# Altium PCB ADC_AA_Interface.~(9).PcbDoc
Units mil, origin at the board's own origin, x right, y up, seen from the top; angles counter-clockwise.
Board outline 2600 x 10000 mil, 6 copper layers (Top Layer, InternalPlane1, MidLayer1, InternalPlane2, InternalPlane3, Bottom Layer); 10 components, 66 nets, 246 pads, 0 vias.
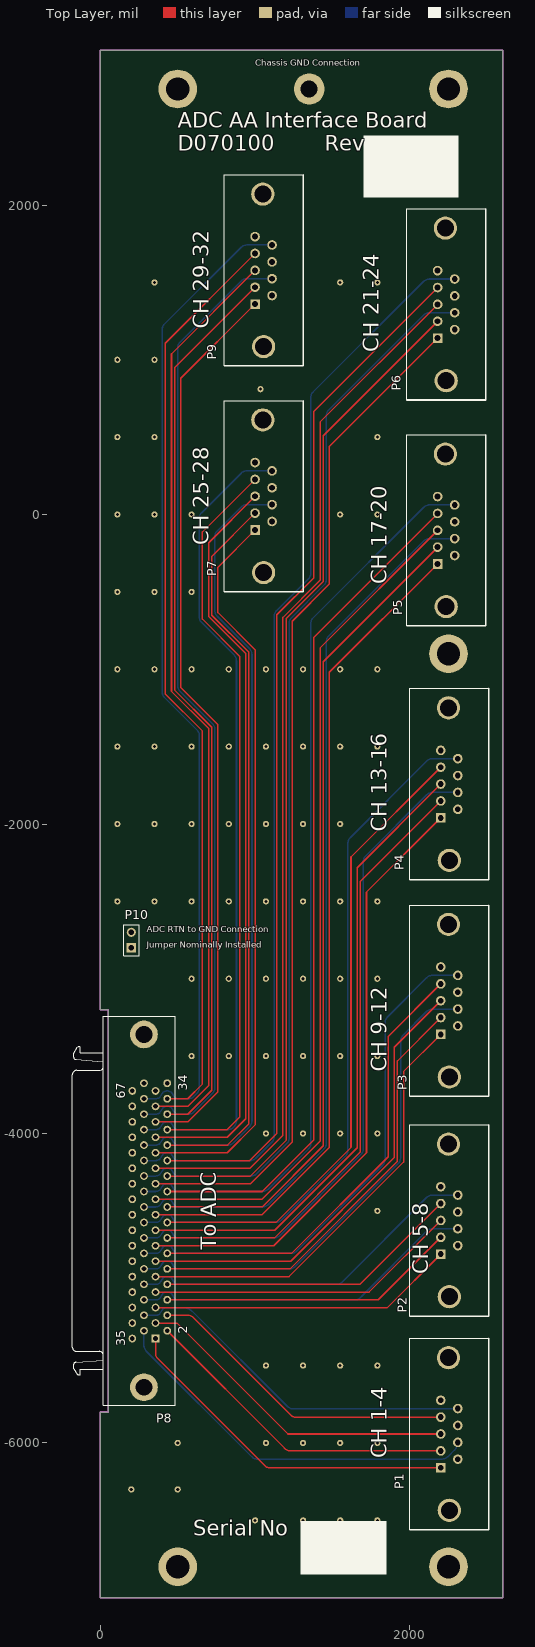
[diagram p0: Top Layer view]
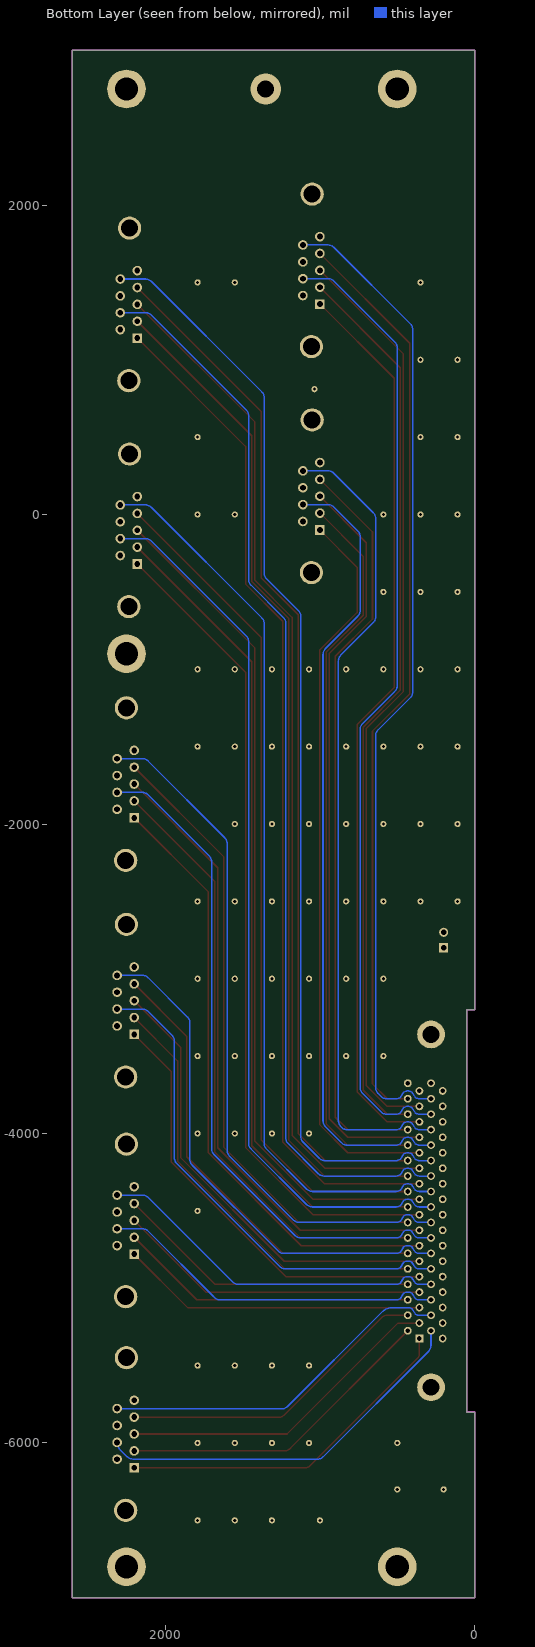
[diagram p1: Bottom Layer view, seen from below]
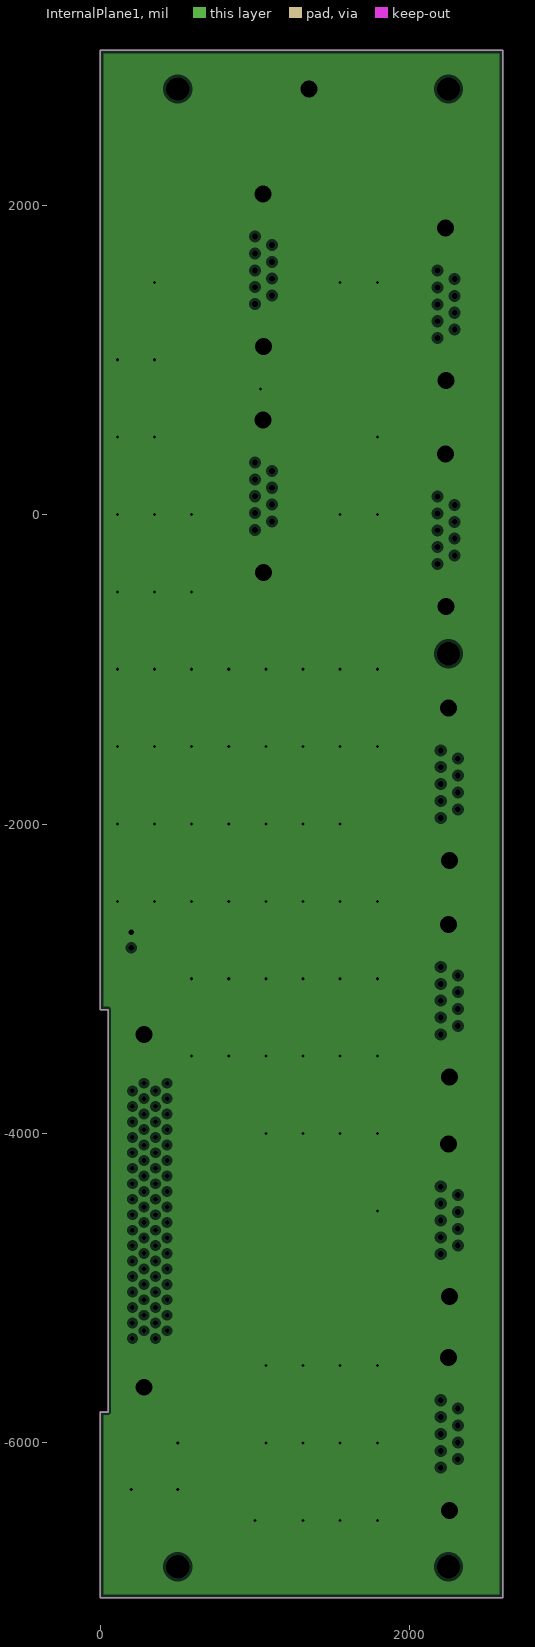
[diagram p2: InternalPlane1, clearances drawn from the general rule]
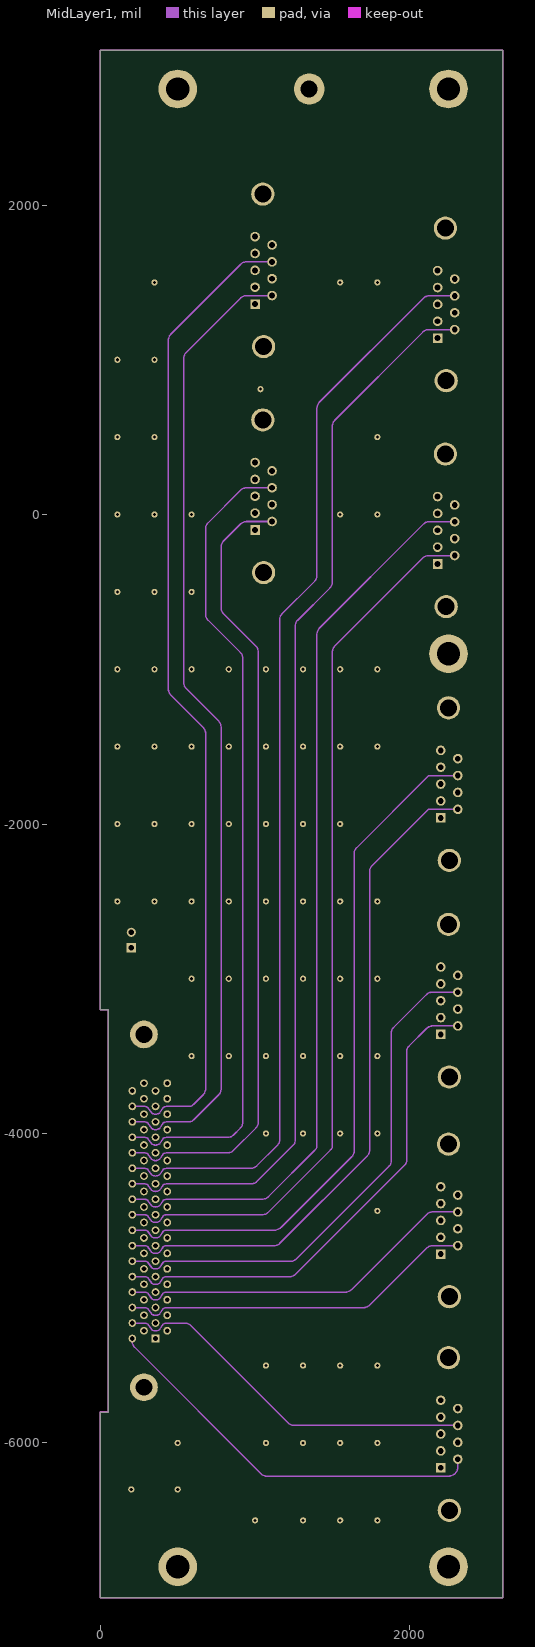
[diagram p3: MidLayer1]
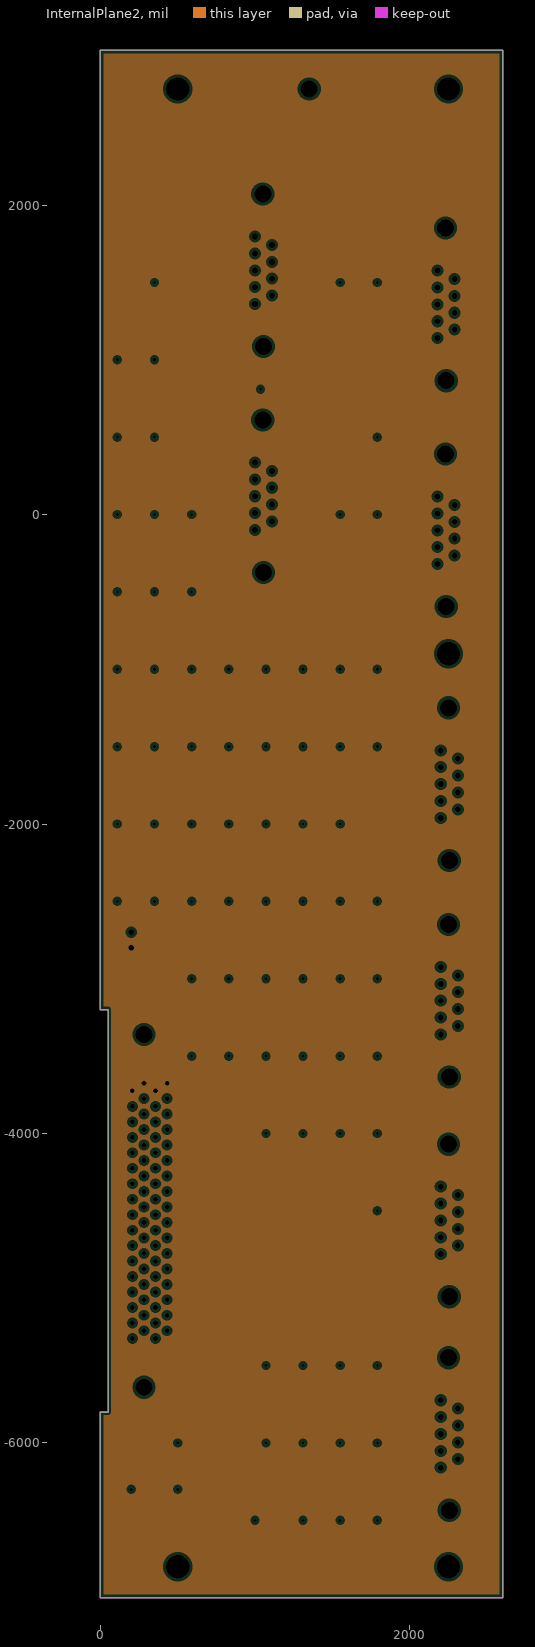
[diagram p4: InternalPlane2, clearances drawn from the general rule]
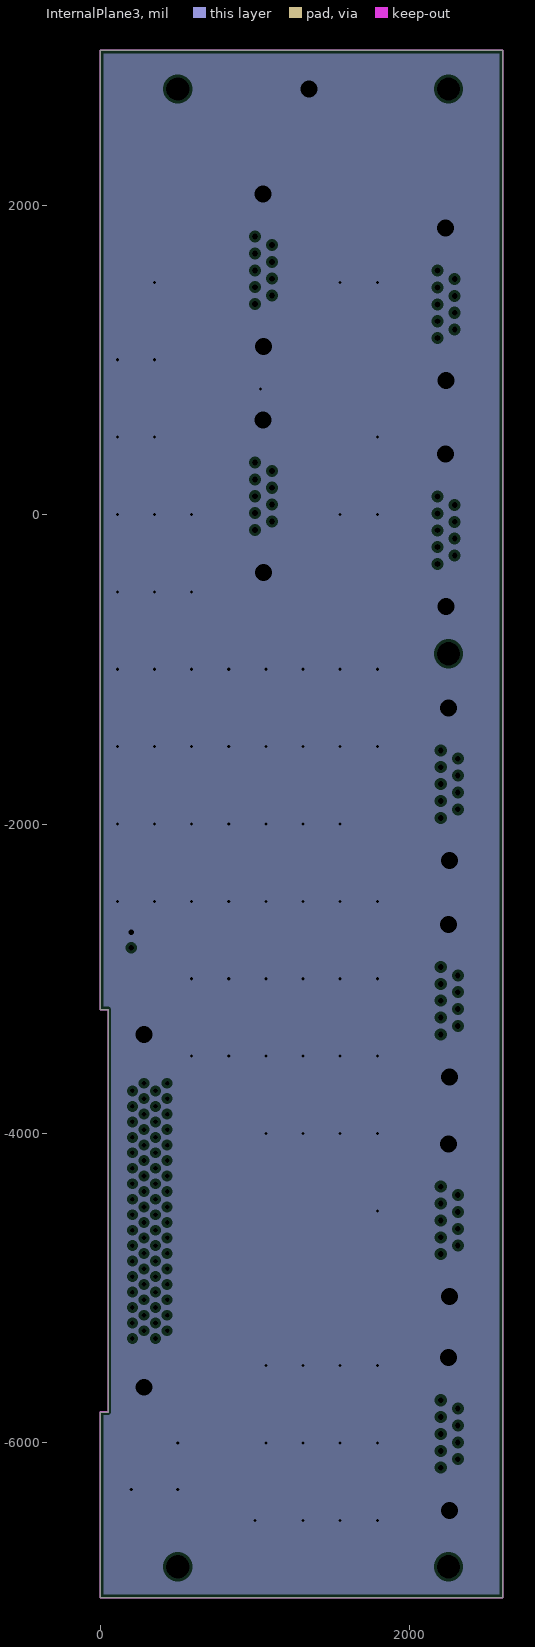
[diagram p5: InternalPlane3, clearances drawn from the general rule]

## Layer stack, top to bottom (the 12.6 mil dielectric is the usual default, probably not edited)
Top Solder: solder mask 0.4, Solder Resist, Dk 3.5
Top Layer: signal copper 1.4
Dielectric1: core 12.6, FR-4, Dk 4.8
InternalPlane1: plane copper 1.4, net GND
Dielectric3: prepreg 12.6, FR-4, Dk 4.8
MidLayer1: signal copper 1.4
Dielectric2: core 12.6, FR-4, Dk 4.8
InternalPlane2: plane copper 1.4, net RTN
Dielectric4: prepreg 12.6, FR-4, Dk 4.8
InternalPlane3: plane copper 1.4, net GND
Dielectric5: core 12.6, FR-4, Dk 4.8
Bottom Layer: signal copper 1.4
Bottom Solder: solder mask 0.4, Solder Resist, Dk 3.5

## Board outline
0,-7000 0,-5800 50,-5800 50,-3200 0,-3200 0,3000 2600,3000 2600,-7000

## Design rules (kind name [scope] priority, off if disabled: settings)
Clearance [All] p1: gap=10 ignorepadtopadclearanceinfootprint=FALSE except(0: Arc-Hole Track-Hole SMDPad-Hole THPad-Hole Via-Hole Fill-Hole Poly-Hole Region-Hole Text-Hole)
FabricationTestPointUsage TestPointUsage [All] p1: valid=0 allowmultiple=FALSE
FabricationTestpoint Testpoint [All] p1: side=3 testpointundercomponent=TRUE minsize=40 maxsize=100 preferedsize=60 minholesize=0 maxholesize=40 preferedholesize=32 testpointgrid=1 allowsidetop=TRUE allowsidebottom=TRUE usegrid=TRUE gridtolerance=0.01
HoleSize [All] p1: absolutevalues=TRUE maxlimit=200 minlimit=1 maxpercent=80.000 minpercent=20.000
PlaneClearance [All] p1: clearance=20
PlaneConnect [All] p1: planeconnectstyle=Relief reliefexpansion=20 reliefentries=4 reliefconductorwidth=10 reliefairgap=10
PolygonConnect [All] p1: connectstyle=Relief reliefconductorwidth=10 reliefentries=4 polygonreliefangle="90 Angle" airgapwidth=10
RoutingVias [All] p1: holewidth=20 width=40 viastyle="Through Hole" minholewidth=20 minwidth=40 maxholewidth=28 maxwidth=50
SolderMaskExpansion [All] p1: expansion=4
Width [All] p1: maxlimit=100 minlimit=10 preferedwidth=10
25 further rules are at their usual default settings.

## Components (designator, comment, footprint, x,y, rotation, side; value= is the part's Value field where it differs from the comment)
P1 "5747871-8" DB9/M 2200,-6160 r270 top
P2 "5747871-8" DB9/M 2200,-4780 r270 top
P3 "5747871-8" DB9/M 2200,-3360 r270 top
P4 "5747871-8" DB9/M 2200,-1960 r270 top
P5 "5747871-8" DB9/M 2180,-320 r270 top
P6 "5747871-8" DB9/M 2180,1140 r270 top
P7 "5747871-8" DB9/M 1000,-100 r270 top
P8 "787082-7" 787082-7 20,-4500 r90 top
P9 "5747871-8" DB9/M 1000,1360 r270 top
P10 "Header 2" HDR1X2 200,-2800 r90 top

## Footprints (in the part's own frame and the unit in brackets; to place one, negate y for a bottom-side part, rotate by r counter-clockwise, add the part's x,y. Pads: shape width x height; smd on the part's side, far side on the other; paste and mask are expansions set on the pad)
787082-7 [mm] "Connector; D Subminiature 050 Series; 68 Position; Right Angle"
  rect 1.27x1.27 hole 0.762: 1(-20.955,-8.555)
  round 1.27 hole 0.762: 2(-19.685,-10.46) 3(-18.415,-8.555) 4(-17.145,-10.46) 5(-15.875,-8.555) 6(-14.605,-10.46) 7(-13.335,-8.555) 8(-12.065,-10.46) 9(-10.795,-8.555) 10(-9.525,-10.46) 11(-8.255,-8.555) 12(-6.985,-10.46) 13(-5.715,-8.555) 14(-4.445,-10.46) 15(-3.175,-8.555) 16(-1.905,-10.46) 17(-0.635,-8.555) 18(0.635,-10.46) 19(1.905,-8.555) 20(3.175,-10.46) 21(4.445,-8.555) 22(5.715,-10.46) 23(6.985,-8.555) 24(8.255,-10.46) 25(9.525,-8.555) 26(10.795,-10.46) 27(12.065,-8.555) 28(13.335,-10.46) 29(14.605,-8.555) 30(15.875,-10.46) 31(17.145,-8.555) 32(18.415,-10.46) 33(19.685,-8.555) 34(20.955,-10.46) 35(-20.955,-4.745) 36(-19.685,-6.65) 37(-18.415,-4.745) 38(-17.145,-6.65) 39(-15.875,-4.745) 40(-14.605,-6.65) 41(-13.335,-4.745) 42(-12.065,-6.65) 43(-10.795,-4.745) 44(-9.525,-6.65) 45(-8.255,-4.745) 46(-6.985,-6.65) 47(-5.715,-4.745) 48(-4.445,-6.65) 49(-3.175,-4.745) 50(-1.905,-6.65) 51(-0.635,-4.745) 52(0.635,-6.65) 53(1.905,-4.745) 54(3.175,-6.65) 55(4.445,-4.745) 56(5.715,-6.65) 57(6.985,-4.745) 58(8.255,-6.65) 59(9.525,-4.745) 60(10.795,-6.65) 61(12.065,-4.745) 62(13.335,-6.65) 63(14.605,-4.745) 64(15.875,-6.65) 65(17.145,-4.745) 66(18.415,-6.65) 67(19.685,-4.745) 68(20.955,-6.65)
  round 4.55 hole 2.77: 69(-28.955,-6.65) 70(28.955,-6.65)
  silkscreen extent -31.95,-11.76 31.95,5.11
DB9/M [mil]
  round 150 hole 110: 0(-711,50) 0(275,55)
  rect 62x62 hole 38: 1(0,0)
  round 62 hole 38: 2(-109,0) 3(-218,0) 4(-327,0) 5(-436,0) 6(-55,110) 7(-164,110) 8(-273,110) 9(-382,110)
  silkscreen extent -836,-200 400,310
HDR1X2 [mm] "Connector; Header; 2 Position"
  rect 1.5x1.5 hole 0.9: 1(0,0)
  round 1.5 hole 0.9: 2(2.54,0)
  silkscreen extent -1.27,-1.27 3.81,1.27

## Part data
P1 P2 P3 P4 P5 P6 P7 P9: library part 788754-1, "Plug Assembly, Size 1, 9 Position, Right Angle, 8.08mm Series, Amplimite"
P8: library part "PE50E-080 Connector", "3M Pak 50 plug connector"
P10: "Header, 2-Pin"

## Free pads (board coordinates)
  round 40 hole 20: 0(500,-6000) 1(1070,-6000) 2(1310,-6500) 2(1310,-6000) 2(1550,-6000) 3(1790,-6000) 4(1070,-5500) 4(1310,-5500) 5(1550,-5500) 6(1790,-5500) 9(1790,-4500) 16(1790,-4000) 17(1790,-3500) 22(1550,-4000) 23(1550,-3500) 24(1550,-3000) 31(1310,-3000) 32(1310,-3500) 33(1790,-3000) 38(830,-3500) 39(830,-3000) 40(830,-2500) 41(350,-2500) 42(590,-2500) 44(590,-3000) 45(1070,-2500) 46(1790,-2500) 47(1310,-2500) 48(1550,-2500) 50(590,-3500) 52(1070,-4000) 52(1310,-4000) 53(1070,-3500) 54(1070,-3000) 55(350,-2000) 56(590,-2000) 57(830,-2000) 58(1070,-2000) 60(1310,-2000) 61(1550,-2000) 62(1550,-1500) 63(1310,-1500) 64(1790,-1500) 64(1790,-1000) 65(1070,-1500) 66(830,-1500) 67(590,-1500) 68(350,-1500) 69(350,-1000) 70(590,-1000) 71(830,-1000) 72(1070,-1000) 73(1310,-1000) 74(1550,-1000) 76(110,1000) 77(110,500) 78(110,0) 78(350,-500) 79(110,-500) 79(590,-500) 80(110,-1000) 81(110,-1500) 82(110,-2000) 83(110,-2500) 83(350,0) 84(590,0) 85(200,-6300) 85(1790,0) 86(500,-6300) 86(1550,0) 87(1000,-6500) 88(350,500) 88(1550,-6500) 89(350,1000) 89(1790,-6500) 90(1035,810) 93(1790,500) 94(1550,1500) 95(1790,1500) 96(350,1500)
  round 200 hole 110: 0(1350,2750)
  round 250 hole 150: 0(2250,-6800) 1(2250,2750) 2(500,2750) 3(500,-6800) 4(2250,-900)

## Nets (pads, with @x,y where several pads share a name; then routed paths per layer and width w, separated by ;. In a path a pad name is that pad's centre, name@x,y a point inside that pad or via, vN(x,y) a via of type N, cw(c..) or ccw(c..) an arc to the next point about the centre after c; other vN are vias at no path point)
GND: P1.0 P2.0 P3.0 P4.0 P5.0 P6.0 P7.0 P8.69 P8.70 P9.0 P10.2 pad.0@500,-6000 pad.0@1350,2750 pad.1@1070,-6000 pad.2@1310,-6000 pad.2@1310,-6500 pad.2@1550,-6000 pad.3@1790,-6000 pad.4@1070,-5500 pad.4@1310,-5500 pad.5 pad.6 pad.9 pad.16 pad.17 pad.22 pad.23 pad.24 pad.31 pad.32 pad.33 pad.38 pad.39 pad.40 pad.41 pad.42 pad.44 pad.45 pad.46 pad.47 pad.48 pad.50 pad.52 pad.53 pad.54 pad.55 pad.56 pad.57 pad.58 pad.60 pad.61 pad.62 pad.63 pad.64 pad.65 pad.66 pad.67 pad.68 pad.69 pad.70 pad.71 pad.72 pad.73 pad.74 pad.76 pad.77 pad.78 pad.79 pad.80 pad.81 pad.82 pad.83 pad.84 pad.85 pad.86 pad.87 pad.88 pad.89 pad.90 pad.93 pad.94 pad.95 pad.96
OUTPUTN1: P1.6 P8.35 | length 2576
  MidLayer1 w10: P8.35 206.81,-5348.16 ccw(c251.84,-5348.16) 220,-5380 1040,-6200 ccw(c1073.8,-6166.2) 1073.8,-6214 2251.92,-6214 ccw(c2251.92,-6155.87) 2293.03,-6196.97 ccw(c2251.96,-6155.96) 2310,-6155.96 P1.6
OUTPUTN2: P1.7 P8.36 | length 2519.9
  Top Layer w10: P1.7@2310,-6020 P1.7
  Bottom Layer w10: P8.36 281.81,-5370 ccw(c334.47,-5370) 297.23,-5407.23 ; 300,-5410 297.23,-5407.23 ; P1.7 cw(c2239.99,-5996) 2289.49,-6045.51 2251.21,-6083.79 cw(c2200,-6032.57) 2200,-6105 1016.21,-6105 cw(c1016.21,-6053.79) 980.03,-6090.03 297.23,-5407.23
OUTPUTN3: P1.8 P8.37 | length 2415.4
  MidLayer1 w10: P8.37 280,-5225 ; 281.81,-5225 cw(c281.81,-5275) 307.3,-5231.99 cw(c281.81,-5275) 307.44,-5232.07 ; 307.28,-5231.82 307.44,-5232.07 ; 406.18,-5232.07 382.54,-5267.87 cw(c356.81,-5225) 331.08,-5267.87 307.44,-5232.07 ; 406.32,-5231.99 cw(c431.81,-5275) 431.81,-5225 545,-5225 cw(c545,-5280.81) 584.46,-5241.35 1213.15,-5870.03 ccw(c1254.16,-5828.96) 1254.16,-5887 ; 1255,-5887 1254.16,-5887 ; P1.8 1254.16,-5887
OUTPUTN4: P1.9 P8.38 | length 2322.5
  Bottom Layer w10: P8.38 355,-5175 ; 356.81,-5175 ccw(c356.81,-5125) 382.3,-5168.01 ; 382.44,-5167.93 406.08,-5132.13 cw(c431.81,-5175) 431.81,-5125 528.58,-5125 cw(c528.58,-5225) 599.29,-5154.29 1210.98,-5765.98 ccw(c1240,-5736.96) 1240,-5778 ; 1230,-5778 1240,-5778 ; P1.9 1240,-5778
OUTPUTN5: P2.6 P8.39 | length 2310.9
  MidLayer1 w10: P8.39 280,-5125 ; 281.81,-5125 cw(c281.81,-5175) 307.3,-5131.99 ; 406.18,-5132.07 382.54,-5167.87 cw(c356.81,-5125) 356.81,-5175 cw(c356.81,-5125) 331.08,-5167.87 307.44,-5132.07 ; 406.32,-5131.99 cw(c431.81,-5175) 431.81,-5125 1703.79,-5125 ccw(c1703.79,-5073.79) 1739.98,-5110.02 2108,-4742 ; 2110.86,-4739.14 2108,-4742 ; P2.6 2145,-4725 ccw(c2145,-4773.28) 2110.88,-4739.12 2108,-4742 ; 307.3,-5131.99 cw(c281.81,-5175) 307.44,-5132.07 ; 307.3,-5131.99 cw(c356.81,-5125) 307.28,-5131.82 307.44,-5132.07
OUTPUTN6: P2.7 P8.40 | length 2256.1
  Bottom Layer w10: P8.40 355,-5075 ; 356.81,-5075 ccw(c356.81,-5025) 382.3,-5068.01 ; 481.18,-5067.93 457.54,-5032.13 ccw(c431.81,-5075) 431.81,-5025 ccw(c431.81,-5075) 406.08,-5032.13 382.44,-5067.93 ; 481.32,-5068.01 ccw(c506.81,-5025) 506.81,-5075 1645,-5075 ccw(c1645,-5024.3) 1680.83,-5060.17 1686,-5055 2110.17,-4630.83 cw(c2146,-4666.7) 2146,-4616 P2.7 ; 382.3,-5068.01 ccw(c356.81,-5025) 382.44,-5067.93 ; 382.3,-5068.01 ccw(c431.81,-5075) 382.28,-5068.18 382.44,-5067.93
OUTPUTN7: P2.8 P8.41 | length 2362.5
  MidLayer1 w10: P8.41 280,-5025 ; 281.81,-5025 cw(c281.81,-5075) 307.3,-5031.99 ; 406.18,-5032.07 382.54,-5067.87 cw(c356.81,-5025) 356.81,-5075 cw(c356.81,-5025) 331.08,-5067.87 307.44,-5032.07 ; 406.32,-5031.99 cw(c431.81,-5075) 431.81,-5025 1585,-5025 ccw(c1585,-4971.89) 1622.54,-5009.46 2106,-4526 ; 2110.86,-4521.14 2106,-4526 ; P2.8 2145,-4507 ccw(c2145,-4555.28) 2110.88,-4521.12 2106,-4526 ; 307.3,-5031.99 cw(c281.81,-5075) 307.44,-5032.07 ; 307.3,-5031.99 cw(c356.81,-5025) 307.28,-5031.82 307.44,-5032.07
OUTPUTN8: P2.9 P8.42 | length 2305
  Bottom Layer w10: P8.42 355,-4975 ; 356.81,-4975 ccw(c356.81,-4925) 382.3,-4968.01 ; 481.18,-4967.93 457.54,-4932.13 ccw(c431.81,-4975) 431.81,-4925 ccw(c431.81,-4975) 406.08,-4932.13 382.44,-4967.93 ; 481.32,-4968.01 ccw(c506.81,-4925) 506.81,-4975 1527,-4975 ccw(c1527,-4924.3) 1562.83,-4960.17 2110.17,-4412.83 cw(c2146,-4448.7) 2146,-4398 P2.9 ; 382.3,-4968.01 ccw(c356.81,-4925) 382.44,-4967.93 ; 382.3,-4968.01 ccw(c431.81,-4975) 382.28,-4968.18 382.44,-4967.93
OUTPUTN9: P3.6 P8.43 | length 3245.8
  MidLayer1 w10: P8.43 280,-4925 ; 281.81,-4925 cw(c281.81,-4975) 307.3,-4931.99 ; 406.18,-4932.07 382.54,-4967.87 cw(c356.81,-4925) 356.81,-4975 cw(c356.81,-4925) 331.08,-4967.87 307.44,-4932.07 ; 406.32,-4931.99 cw(c431.81,-4975) 431.81,-4925 1225,-4925 ccw(c1225,-4876.72) 1259.12,-4910.88 ; 1259.14,-4910.86 1970,-4200 ccw(c1945.86,-4175.86) 1980,-4175.86 1980,-3471.21 cw(c2031.21,-3471.21) 1994.99,-3435.01 2110.01,-3319.99 cw(c2146.21,-3356.21) 2146.21,-3305 ; 2150,-3305 2146.21,-3305 ; P3.6 2146.21,-3305 ; 307.3,-4931.99 cw(c356.81,-4925) 307.28,-4931.82 307.44,-4932.07 ; 307.3,-4931.99 cw(c281.81,-4975) 307.44,-4932.07
OUTPUTN10: P3.7 P8.44 | length 3225.1
  Bottom Layer w10: P8.44 355,-4875 ; 356.81,-4875 ccw(c356.81,-4825) 382.3,-4868.01 ; 481.18,-4867.93 457.54,-4832.13 ccw(c431.81,-4875) 431.81,-4825 ccw(c431.81,-4875) 406.08,-4832.13 382.44,-4867.93 ; 481.32,-4868.01 ccw(c506.81,-4825) 506.81,-4875 1224,-4875 ccw(c1224,-4824.3) 1259.83,-4860.17 1925.17,-4194.83 ccw(c1889.3,-4159) 1940,-4159 1940,-3402 cw(c1990.7,-3402) 1954.83,-3366.17 2110.17,-3210.83 cw(c2146,-3246.7) 2146,-3196 P3.7 ; 382.3,-4868.01 ccw(c356.81,-4825) 382.44,-4867.93 ; 382.3,-4868.01 ccw(c431.81,-4875) 382.28,-4868.18 382.44,-4867.93
OUTPUTN11: P3.8 P8.45 | length 3365.1
  MidLayer1 w10: P8.45 280,-4825 ; 281.81,-4825 cw(c281.81,-4875) 307.3,-4831.99 ; 406.18,-4832.07 382.54,-4867.87 cw(c356.81,-4825) 356.81,-4875 cw(c356.81,-4825) 331.08,-4867.87 307.44,-4832.07 ; 406.32,-4831.99 cw(c431.81,-4875) 431.81,-4825 1235,-4825 ccw(c1235,-4783.96) 1264.01,-4812.99 1867.98,-4209.02 ccw(c1838.96,-4180) 1880,-4180 1880,-3351.21 cw(c1931.21,-3351.21) 1894.99,-3315.01 2107.45,-3102.55 cw(c2145,-3140.11) 2145,-3087 P3.8 ; 307.3,-4831.99 cw(c356.81,-4825) 307.28,-4831.82 307.44,-4832.07 ; 307.3,-4831.99 cw(c281.81,-4875) 307.44,-4832.07
OUTPUTN12: P3.9 P8.46 | length 3349
  Bottom Layer w10: P8.46 355,-4775 ; 356.81,-4775 ccw(c356.81,-4725) 382.3,-4768.01 ; 481.18,-4767.93 457.54,-4732.13 ccw(c431.81,-4775) 431.81,-4725 ccw(c431.81,-4775) 406.08,-4732.13 382.44,-4767.93 ; 481.32,-4768.01 ccw(c506.81,-4725) 506.81,-4775 1234,-4775 ccw(c1234,-4724.3) 1269.83,-4760.17 1825.17,-4204.83 ccw(c1789.3,-4169) 1840,-4169 1840,-3284 cw(c1890.7,-3284) 1854.83,-3248.17 2110.17,-2992.83 cw(c2146,-3028.7) 2146,-2978 P3.9 ; 382.3,-4768.01 ccw(c356.81,-4725) 382.44,-4767.93 ; 382.3,-4768.01 ccw(c431.81,-4775) 382.28,-4768.18 382.44,-4767.93
OUTPUTN13: P4.6 P8.47 | length 4397.4
  MidLayer1 w10: P8.47 280,-4725 ; 281.81,-4725 cw(c281.81,-4775) 307.3,-4731.99 ; 406.18,-4732.07 382.54,-4767.87 cw(c356.81,-4725) 356.81,-4775 cw(c356.81,-4725) 331.08,-4767.87 307.44,-4732.07 ; 406.32,-4731.99 cw(c431.81,-4775) 431.81,-4725 1123.79,-4725 ccw(c1123.79,-4673.79) 1159.98,-4710.02 1725.03,-4144.97 ccw(c1688.79,-4108.79) 1740,-4108.81 ; 1740,-4105 1740,-4108.79 ; 1740,-2315 1740,-2306.21 ; 1755,-2270 ccw(c1791.21,-2306.21) 1754.94,-2270.06 ; 2120,-1905 1754.94,-2270.06 ; 2123,-1905 P4.6 ; 307.3,-4731.99 cw(c356.81,-4725) 307.28,-4731.82 307.44,-4732.07 ; 307.3,-4731.99 cw(c281.81,-4775) 307.44,-4732.07 ; 1740,-4108.81 1740,-2306.19 ; 1740,-2306.19 cw(c1791.21,-2306.21) 1754.94,-2270.06
OUTPUTN14: P4.7 P8.48 | length 4366.6
  Bottom Layer w10: P8.48 355,-4675 ; 356.81,-4675 ccw(c356.81,-4625) 382.3,-4668.01 ; 481.18,-4667.93 457.54,-4632.13 ccw(c431.81,-4675) 431.81,-4625 ccw(c431.81,-4675) 406.08,-4632.13 382.44,-4667.93 ; 481.32,-4668.01 ccw(c506.81,-4625) 506.81,-4675 1124,-4675 ccw(c1124,-4624.3) 1159.83,-4660.17 1685.17,-4134.83 ccw(c1649.3,-4099) 1700,-4099 1700,-2242 cw(c1750.7,-2242) 1714.83,-2206.17 2110.17,-1810.83 cw(c2146,-1846.7) 2146,-1796 P4.7 ; 382.3,-4668.01 ccw(c356.81,-4625) 382.44,-4667.93 ; 382.3,-4668.01 ccw(c431.81,-4675) 382.28,-4668.18 382.44,-4667.93
OUTPUTN15: P4.8 P8.49 | length 4512.4
  MidLayer1 w10: P8.49 280,-4625 ; 281.81,-4625 cw(c281.81,-4675) 307.3,-4631.99 ; 406.18,-4632.07 382.54,-4667.87 cw(c356.81,-4625) 356.81,-4675 cw(c356.81,-4625) 331.08,-4667.87 307.44,-4632.07 ; 406.32,-4631.99 cw(c431.81,-4675) 431.81,-4625 1123.79,-4625 ccw(c1123.79,-4561.72) 1168.46,-4606.54 ; 1170,-4605 1168.54,-4606.46 cw(c1123.79,-4561.72) 1168.46,-4606.54 ; 1640,-2195 1640,-2191.21 ; P4.8 2123,-1687 1655,-2155 ccw(c1691.21,-2191.21) 1640,-2191.2 ; 307.3,-4631.99 cw(c281.81,-4675) 307.44,-4632.07 ; 307.3,-4631.99 cw(c356.81,-4625) 307.28,-4631.82 307.44,-4632.07 ; 1168.46,-4606.54 1625,-4150 1625.86,-4149.14 ccw(c1591.72,-4115) 1640,-4115.01 1640,-2191.21
OUTPUTN16: P4.9 P8.50 | length 4490.4
  Bottom Layer w10: P8.50 355,-4575 ; 356.81,-4575 ccw(c356.81,-4525) 382.3,-4568.01 ; 481.18,-4567.93 457.54,-4532.13 ccw(c431.81,-4575) 431.81,-4525 ccw(c431.81,-4575) 406.08,-4532.13 382.44,-4567.93 ; 481.32,-4568.01 ccw(c506.81,-4525) 506.81,-4575 1134,-4575 ccw(c1134,-4524.3) 1169.83,-4560.17 1585.17,-4144.83 ccw(c1549.3,-4109) 1600,-4109 1600,-2124 cw(c1650.7,-2124) 1614.83,-2088.17 2110.17,-1592.83 cw(c2146,-1628.7) 2146,-1578 P4.9 ; 382.3,-4568.01 ccw(c356.81,-4525) 382.44,-4567.93 ; 382.3,-4568.01 ccw(c431.81,-4575) 382.28,-4568.18 382.44,-4567.93
OUTPUTN17: P5.6 P8.51 | length 5772.2
  MidLayer1 w10: P8.51 280,-4525 ; 281.81,-4525 cw(c281.81,-4575) 307.3,-4531.99 ; 406.18,-4532.07 382.54,-4567.87 cw(c356.81,-4525) 356.81,-4575 cw(c356.81,-4525) 331.08,-4567.87 307.44,-4532.07 ; 406.32,-4531.99 cw(c431.81,-4575) 431.81,-4525 1045,-4525 ccw(c1045,-4467.06) 1085.97,-4508.03 1486.57,-4107.43 ; 1486.59,-4107.41 ccw(c1454.13,-4075) 1500,-4075 1500,-895 1500,-886.21 cw(c1551.21,-886.21) 1514.99,-850.01 2080,-285 2082.32,-282.68 cw(c2125,-325.36) 2125,-265 P5.6 ; 307.3,-4531.99 cw(c281.81,-4575) 307.44,-4532.07 ; 307.3,-4531.99 cw(c356.81,-4525) 307.28,-4531.82 307.44,-4532.07
OUTPUTN18: P5.7 P8.52 | length 5754.3
  Bottom Layer w10: P8.52 355,-4475 ; 356.81,-4475 ccw(c356.81,-4425) 382.3,-4468.01 ; 481.18,-4467.93 457.54,-4432.13 ccw(c431.81,-4475) 431.81,-4425 ccw(c431.81,-4475) 406.08,-4432.13 382.44,-4467.93 ; 481.32,-4468.01 ccw(c506.81,-4425) 506.81,-4475 1049,-4475 ccw(c1049,-4424.3) 1084.83,-4460.17 1445.17,-4099.83 ccw(c1409.3,-4064) 1460,-4064 1460,-822 cw(c1510.7,-822) 1474.83,-786.17 2090.17,-170.83 cw(c2126,-206.7) 2126,-156 P5.7 ; 382.3,-4468.01 ccw(c356.81,-4425) 382.44,-4467.93 ; 382.3,-4468.01 ccw(c431.81,-4475) 382.28,-4468.18 382.44,-4467.93
OUTPUTN19: P5.8 P8.53 | length 5898.5
  MidLayer1 w10: P8.53 280,-4425 ; 281.81,-4425 cw(c281.81,-4475) 307.3,-4431.99 ; 406.18,-4432.07 382.54,-4467.87 cw(c356.81,-4425) 356.81,-4475 cw(c356.81,-4425) 331.08,-4467.87 307.44,-4432.07 ; 406.32,-4431.99 cw(c431.81,-4475) 431.81,-4425 1045.25,-4425 ccw(c1045.25,-4365.25) 1087.5,-4407.5 1385.86,-4109.14 ccw(c1351.72,-4075) 1400,-4075.02 1400,-771.21 ; 1400,-780 1400,-771.21 ; P5.8 2120,-47 ccw(c2120,-88.04) 2090.98,-59.02 2085,-65 1415,-735 ccw(c1451.21,-771.21) 1400,-771.19 ; 307.3,-4431.99 cw(c281.81,-4475) 307.44,-4432.07 ; 307.3,-4431.99 cw(c356.81,-4425) 307.28,-4431.82 307.44,-4432.07
OUTPUTN20: P5.9 P8.54 | length 5872.3
  Bottom Layer w10: P8.54 355,-4375 ; 356.81,-4375 ccw(c356.81,-4325) 382.3,-4368.01 ; 481.18,-4367.93 457.54,-4332.13 ccw(c431.81,-4375) 431.81,-4325 ccw(c431.81,-4375) 406.08,-4332.13 382.44,-4367.93 ; 481.32,-4368.01 ccw(c506.81,-4325) 506.81,-4375 1049,-4375 ccw(c1049,-4324.3) 1084.83,-4360.17 1345.17,-4099.83 ccw(c1309.3,-4064) 1360,-4064 1360,-704 cw(c1410.7,-704) 1374.83,-668.17 2090.17,47.17 cw(c2126,11.3) 2126,62 P5.9 ; 382.3,-4368.01 ccw(c356.81,-4325) 382.44,-4367.93 ; 382.3,-4368.01 ccw(c431.81,-4375) 382.28,-4368.18 382.44,-4367.93
OUTPUTN21: P6.6 P8.55 | length 6987.1
  MidLayer1 w10: P8.55 280,-4325 ; 281.81,-4325 cw(c281.81,-4375) 307.3,-4331.99 ; 406.18,-4332.07 382.54,-4367.87 cw(c356.81,-4325) 356.81,-4375 cw(c356.81,-4325) 331.08,-4367.87 307.44,-4332.07 ; 406.32,-4331.99 cw(c431.81,-4375) 431.81,-4325 975,-4325 ccw(c975,-4271.89) 1012.54,-4309.46 1247,-4075 ccw(c1215.62,-4043.62) 1260,-4043.62 1260,-4040 1260,-720 1260,-719.21 cw(c1311.21,-719.21) 1275,-683 1483.75,-474.25 ; 1483,-475 1483.74,-474.26 ; P6.6 2121.21,1195 ccw(c2121.21,1143.79) 2085,1180 1515,610 ccw(c1551.21,573.79) 1500,573.79 1500,-435 cw(c1444.48,-435) 1483.75,-474.25 ; 307.3,-4331.99 cw(c281.81,-4375) 307.44,-4332.07 ; 307.3,-4331.99 cw(c356.81,-4325) 307.28,-4331.82 307.44,-4332.07
OUTPUTN22: P6.7 P8.56 | length 6966.2
  Bottom Layer w10: P8.56 355,-4275 ; 356.81,-4275 ccw(c356.81,-4225) 382.3,-4268.01 ; 481.18,-4267.93 457.54,-4232.13 ccw(c431.81,-4275) 431.81,-4225 ccw(c431.81,-4275) 406.08,-4232.13 382.44,-4267.93 ; 481.32,-4268.01 ccw(c506.81,-4225) 506.81,-4275 974,-4275 ccw(c974,-4224.3) 1009.83,-4260.17 1205.17,-4064.83 ccw(c1169.3,-4029) 1220,-4029 1220,-702.43 cw(c1270.7,-702.43) 1234.76,-666.67 ; 1234.83,-666.6 ccw(c1270.7,-702.43) 1234.76,-666.67 ; 1474.82,673.82 ccw(c1510.7,638) 1460,638 1460,-420.43 cw(c1409.3,-420.43) 1445.17,-456.26 1234.76,-666.67 ; 1474.83,673.83 2090.17,1289.17 cw(c2126,1253.3) 2126,1304 P6.7 ; 382.3,-4268.01 ccw(c356.81,-4225) 382.44,-4267.93 ; 382.3,-4268.01 ccw(c431.81,-4275) 382.28,-4268.18 382.44,-4267.93
OUTPUTN23: P6.8 P8.57 | length 7103.5
  MidLayer1 w10: P8.57 280,-4225 ; 281.81,-4225 cw(c281.81,-4275) 307.3,-4231.99 ; 406.18,-4232.07 382.54,-4267.87 cw(c356.81,-4225) 356.81,-4275 cw(c356.81,-4225) 331.08,-4267.87 307.44,-4232.07 ; 406.32,-4231.99 cw(c431.81,-4275) 431.81,-4225 975,-4225 ccw(c975,-4176.72) 1009.12,-4210.88 ; 1009.14,-4210.86 1145.86,-4074.14 ccw(c1111.72,-4040) 1160,-4040 1160,-675 1160,-672.95 cw(c1199.53,-672.95) 1171.56,-645.02 1381.23,-435.35 ccw(c1335.84,-390) 1400,-390.44 ; 1380,-436.58 1381.21,-435.37 ; 1400,-390 cw(c1335.84,-390) 1400,-390.44 ; P6.8 2124.21,1413 ccw(c2124.21,1361.79) 2088,1398 1415,725 ccw(c1451.21,688.79) 1400,688.79 1400,-380 1400,-390.44 ; 307.3,-4231.99 cw(c356.81,-4225) 307.28,-4231.82 307.44,-4232.07 ; 307.3,-4231.99 cw(c281.81,-4275) 307.44,-4232.07
OUTPUTN24: P6.9 P8.58 | length 7081.4
  Bottom Layer w10: P8.58 355,-4175 ; 356.81,-4175 ccw(c356.81,-4125) 382.3,-4168.01 ; 481.18,-4167.93 457.54,-4132.13 ccw(c431.81,-4175) 431.81,-4125 ccw(c431.81,-4175) 406.08,-4132.13 382.44,-4167.93 ; 481.32,-4168.01 ccw(c506.81,-4125) 506.81,-4175 969,-4175 ccw(c969,-4124.3) 1004.83,-4160.17 1108.09,-4056.91 ccw(c1072.22,-4021.08) 1122.92,-4021.08 1122.92,-658.09 cw(c1173.62,-658.09) 1137.66,-622.35 ; 1137.74,-622.27 ccw(c1173.62,-658.09) 1137.66,-622.35 ; 1374.83,791.83 ccw(c1410.7,756) 1374.69,791.69 ; P6.9 2126,1522 ccw(c2126,1471.3) 2090.17,1507.17 1374.69,791.69 ; 382.3,-4168.01 ccw(c356.81,-4125) 382.44,-4167.93 ; 382.3,-4168.01 ccw(c431.81,-4175) 382.28,-4168.18 382.44,-4167.93 ; 1137.66,-622.35 1345.17,-414.84 ccw(c1309.3,-379.01) 1360,-379.01 1360,756 cw(c1410.7,756) 1374.69,791.69
OUTPUTN25: P7.6 P8.59 | length 5165.2
  MidLayer1 w10: P8.59 280,-4125 ; 281.81,-4125 cw(c281.81,-4175) 307.3,-4131.99 ; 406.18,-4132.07 382.54,-4167.87 cw(c356.81,-4125) 356.81,-4175 cw(c356.81,-4125) 331.08,-4167.87 307.44,-4132.07 ; 406.32,-4131.99 cw(c431.81,-4175) 431.81,-4125 820,-4125 ccw(c820,-4064.64) 862.68,-4107.32 1005.86,-3964.14 ; 1005.88,-3964.12 ccw(c971.72,-3930) 1020,-3930 1020,-2792 1020,-1500 1020,-886.45 ; 1020,-886.66 ccw(c968.79,-886.66) 1020,-886.45 ; P7.6 944.21,-45 ccw(c944.21,-96.21) 908,-60 795,-173 ccw(c831.21,-209.21) 780,-209.21 780,-604.23 ccw(c831.21,-604.23) 795,-640.44 1005,-850.44 cw(c968.79,-886.66) 1020,-886.45 ; 307.3,-4131.99 cw(c281.81,-4175) 307.44,-4132.07 ; 307.3,-4131.99 cw(c356.81,-4125) 307.28,-4131.82 307.44,-4132.07
OUTPUTN26: P7.7 P8.60 | length 5148.4
  Bottom Layer w10: P8.60 355,-4075 ; 356.81,-4075 ccw(c356.81,-4025) 382.3,-4068.01 ; 481.18,-4067.93 457.54,-4032.13 ccw(c431.81,-4075) 431.81,-4025 ccw(c431.81,-4075) 406.08,-4032.13 382.44,-4067.93 ; 481.32,-4068.01 ccw(c506.81,-4025) 506.81,-4075 824,-4075 ccw(c824,-4024.3) 859.83,-4060.17 965.17,-3954.83 ccw(c929.3,-3919) 980,-3919 980,-2785 980,-1500 980,-902.81 ; 980,-903.01 ccw(c929.3,-903.01) 980,-902.81 ; P7.7 946,64 ccw(c946,13.3) 910.17,49.17 754.83,-106.17 ccw(c790.7,-142) 740,-142 740,-621.01 ccw(c790.7,-621.01) 754.83,-656.84 965.17,-867.18 cw(c929.3,-903.01) 980,-902.81 ; 382.3,-4068.01 ccw(c356.81,-4025) 382.44,-4067.93 ; 382.3,-4068.01 ccw(c431.81,-4075) 382.28,-4068.18 382.44,-4067.93
OUTPUTN27: P7.8 P8.61 | length 5283.7
  MidLayer1 w10: P8.61 280,-4025 ; 281.81,-4025 cw(c281.81,-4075) 307.3,-4031.99 ; 406.18,-4032.07 382.54,-4067.87 cw(c356.81,-4025) 356.81,-4075 cw(c356.81,-4025) 331.08,-4067.87 307.44,-4032.07 ; 406.32,-4031.99 cw(c431.81,-4075) 431.81,-4025 825,-4025 ccw(c825,-3976.72) 859.12,-4010.88 ; 859.14,-4010.86 905.01,-3964.99 ccw(c868.79,-3928.79) 920,-3928.79 920,-2777.5 920,-1500 920,-927.85 ; 920,-928.08 ccw(c868.79,-928.08) 920,-927.85 ; P7.8 944.21,173 ccw(c944.21,121.79) 908,158 695,-55 ccw(c731.21,-91.21) 680,-91.21 680,-645.65 ccw(c731.21,-645.65) 695,-681.86 905,-891.86 cw(c868.79,-928.08) 920,-927.85 ; 307.3,-4031.99 cw(c281.81,-4075) 307.44,-4032.07 ; 307.3,-4031.99 cw(c356.81,-4025) 307.28,-4031.82 307.44,-4032.07
OUTPUTN28: P7.9 P8.62 | length 5266.2
  Bottom Layer w10: P8.62 355,-3975 ; 356.81,-3975 ccw(c356.81,-3925) 382.3,-3968.01 ; 481.18,-3967.93 457.54,-3932.13 ccw(c431.81,-3975) 431.81,-3925 ccw(c431.81,-3975) 406.08,-3932.13 382.44,-3967.93 ; 481.32,-3968.01 ccw(c506.81,-3925) 506.81,-3975 824,-3975 ccw(c824,-3924.3) 859.83,-3960.17 865.17,-3954.83 ccw(c829.3,-3919) 880,-3919 880,-2715.75 880,-1500 880,-944.43 ccw(c829.3,-944.43) 865.17,-908.6 654.83,-698.26 cw(c690.7,-662.43) 640,-662.43 640,-24 cw(c690.7,-24) 654.83,11.83 910.17,267.17 cw(c946,231.3) 946,282 P7.9 ; 382.3,-3968.01 ccw(c356.81,-3925) 382.44,-3967.93 ; 382.3,-3968.01 ccw(c431.81,-3975) 382.28,-3968.18 382.44,-3967.93
OUTPUTN29: P8.63 P9.6 | length 6280
  MidLayer1 w10: P8.63 280,-3925 ; 281.81,-3925 cw(c281.81,-3975) 307.3,-3931.99 ; 406.18,-3932.07 382.54,-3967.87 cw(c356.81,-3925) 356.81,-3975 cw(c356.81,-3925) 331.08,-3967.87 307.44,-3932.07 ; 406.32,-3931.99 cw(c431.81,-3975) 431.81,-3925 570,-3925 ccw(c570,-3876.72) 604.12,-3910.88 ; 604.14,-3910.86 765.86,-3749.14 ccw(c731.72,-3715) 780,-3715.01 780,-1371.21 ; 780,-1375 780,-1371.21 ; P9.6 944.21,1415 ccw(c944.21,1363.79) 908,1400 555,1047 ccw(c591.21,1010.79) 540,1010.81 540,-1088.79 ccw(c591.21,-1088.79) 555,-1125 765,-1335 cw(c728.79,-1371.21) 780,-1371.21 ; 307.3,-3931.99 cw(c356.81,-3925) 307.28,-3931.82 307.44,-3932.07 ; 307.3,-3931.99 cw(c281.81,-3975) 307.44,-3932.07
OUTPUTN30: P8.64 P9.7 | length 6259
  Bottom Layer w10: P8.64 355,-3875 ; 356.81,-3875 ccw(c356.81,-3825) 382.3,-3868.01 ; 481.18,-3867.93 457.54,-3832.13 ccw(c431.81,-3875) 431.81,-3825 ccw(c431.81,-3875) 406.08,-3832.13 382.44,-3867.93 ; 481.32,-3868.01 ccw(c506.81,-3825) 506.81,-3875 569,-3875 ccw(c569,-3824.3) 604.83,-3860.17 725.17,-3739.83 ccw(c689.3,-3704) 740,-3704.1 ; 740,-3704 cw(c689.3,-3704) 740,-3704.1 ; P9.7 946,1524 ccw(c946,1473.3) 910.17,1509.17 514.83,1113.83 ccw(c550.7,1078) 500,1078 500,-1105.57 ccw(c550.7,-1105.57) 514.83,-1141.4 725.17,-1351.74 cw(c689.3,-1387.57) 740,-1387.57 740,-3704.1 ; 382.3,-3868.01 ccw(c356.81,-3825) 382.44,-3867.93 ; 382.3,-3868.01 ccw(c431.81,-3875) 382.28,-3868.18 382.44,-3867.93
OUTPUTN31: P8.65 P9.8 | length 6394.1
  MidLayer1 w10: P8.65 280,-3825 ; 281.81,-3825 cw(c281.81,-3875) 307.3,-3831.99 ; 406.18,-3832.07 382.54,-3867.87 cw(c356.81,-3825) 356.81,-3875 cw(c356.81,-3825) 331.08,-3867.87 307.44,-3832.07 ; 406.32,-3831.99 cw(c431.81,-3875) 431.81,-3825 570,-3825 ccw(c570,-3776.72) 604.12,-3810.88 ; 604.14,-3810.86 665.03,-3749.97 ccw(c628.79,-3713.79) 680,-3713.8 680,-1412.63 ccw(c628.79,-1412.63) 665,-1376.42 455,-1166.42 cw(c491.21,-1130.21) 440,-1130.21 440,-1125 440,1050 440,1128.79 cw(c491.21,1128.79) 455,1165 908,1618 cw(c944.21,1581.79) 944.21,1633 P9.8 ; 307.3,-3831.99 cw(c356.81,-3825) 307.28,-3831.82 307.44,-3832.07 ; 307.3,-3831.99 cw(c281.81,-3875) 307.44,-3832.07
OUTPUTN32: P8.66 P9.9 | length 6377
  Bottom Layer w10: P8.66 355,-3775 ; 356.81,-3775 ccw(c356.81,-3725) 382.3,-3768.01 ; 481.18,-3767.93 457.54,-3732.13 ccw(c431.81,-3775) 431.81,-3725 ccw(c431.81,-3775) 406.08,-3732.13 382.44,-3767.93 ; 481.32,-3768.01 ccw(c506.81,-3725) 506.81,-3775 569,-3775 ccw(c569,-3724.3) 604.83,-3760.17 625.17,-3739.83 ccw(c589.3,-3704) 640,-3704.1 ; 640,-3704 cw(c589.3,-3704) 640,-3704.1 ; P9.9 946,1742 ccw(c946,1691.3) 910.17,1727.17 414.83,1231.83 ccw(c450.7,1196) 400,1196 400,-1146.99 ccw(c450.7,-1146.99) 414.83,-1182.82 625.17,-1393.16 cw(c589.3,-1428.99) 640,-1428.99 640,-3704.1 ; 382.3,-3768.01 ccw(c356.81,-3725) 382.44,-3767.93 ; 382.3,-3768.01 ccw(c431.81,-3775) 382.28,-3768.18 382.44,-3767.93
OUTPUTP1: P1.1 P8.1 | length 2253.2
  Top Layer w10: P8.1 356.81,-5420 356.81,-5421.44 ccw(c401.84,-5421.44) 370,-5453.28 1066.72,-6150 1067.32,-6150.61 ; 1067.33,-6150.61 ccw(c1090,-6127.93) 1090,-6160 P1.1
OUTPUTP2: P1.2 P8.2 | length 2087.3
  Top Layer w10: P8.2 1190,-6033.19 1192.12,-6035.31 ccw(c1230,-5997.43) 1230,-6051 P1.2
OUTPUTP3: P1.3 P8.3 | length 2140.2
  Top Layer w10: P8.3 495,-5225 1212,-5942 P1.3
OUTPUTP4: P1.4 P8.4 | length 2037.2
  Top Layer w10: P8.4 567.62,-5175 cw(c567.62,-5221.51) 600.51,-5188.62 1234.19,-5822.31 ccw(c1260,-5796.5) 1260,-5833 P1.4
OUTPUTP5: P2.1 P8.5 | length 1986.1
  Top Layer w10: P8.5 1855,-5125 P2.1
OUTPUTP6: P2.2 P8.6 | length 1935.5
  Top Layer w10: P8.6 1796,-5075 P2.2
OUTPUTP7: P2.3 P8.7 | length 2035
  Top Layer w10: P8.7 1737,-5025 P2.3
OUTPUTP8: P2.4 P8.8 | length 1984.4
  Top Layer w10: P8.8 1678,-4975 P2.4
OUTPUTP9: P3.1 P8.9 | length 2834.1
  Top Layer w10: P8.9 1220,-4925 1960,-4185 1960,-3600 P3.1
OUTPUTP10: P3.2 P8.10 | length 2821
  Top Layer w10: P8.10 1225,-4875 1920,-4180 1920,-3531 P3.2
OUTPUTP11: P3.3 P8.11 | length 2958
  Top Layer w10: P8.11 1230,-4825 1900,-4155 1900,-3442 P3.3
OUTPUTP12: P3.4 P8.12 | length 2958.5
  Top Layer w10: P8.12 1236,-4775 1860,-4151 1860,-3373 P3.4 P3.4@2187,-3033
OUTPUTP13: P4.1 P8.13 | length 3975.5
  Top Layer w10: P8.13 1120,-4725 1720,-4125 1720,-2440 P4.1
OUTPUTP14: P4.2 P8.14 | length 3962.5
  Top Layer w10: P8.14 1125,-4675 1680,-4120 1680,-2371 P4.2
OUTPUTP15: P4.3 P8.15 | length 4097.6
  Top Layer w10: P8.15 1127,-4625 1660,-4092 1660,-2282 P4.3
OUTPUTP16: P4.4 P8.16 | length 4086.3
  Top Layer w10: P8.16 1135,-4575 1620,-4090 1620,-2213 P4.4
OUTPUTP17: P5.1 P8.17 | length 5363.3
  Top Layer w10: P8.17 1045,-4525 1480,-4090 1480,-1020 P5.1
OUTPUTP18: P5.2 P8.18 | length 5347.2
  Top Layer w10: P8.18 1050.14,-4472.73 1440,-4080 1440,-951 P5.2
OUTPUTP19: P5.3 P8.19 | length 5481.3
  Top Layer w10: P8.19 1045,-4425 1420,-4050 1420,-862 P5.3
OUTPUTP20: P5.4 P8.20 | length 5465.9
  Top Layer w10: P8.20 1046,-4375 1380,-4041 1380,-793 P5.4
OUTPUTP21: P6.1 P8.21 | length 6579.4
  Top Layer w10: P8.21 970,-4325 1240,-4055 1240,-689.72 1480,-449.71 1480,440 P6.1
OUTPUTP22: P6.2 P8.22 | length 6563.4
  Top Layer w10: P8.22 970,-4275 1200,-4045 1200,-4030 1200,-673.15 1440,-433.15 1440,509 P6.2
OUTPUTP23: P6.3 P8.23 | length 6695.6
  Top Layer w10: P8.23 967,-4225 1180,-4012 1180,-664.86 1420,-424.86 1420,598 P6.3
OUTPUTP24: P6.4 P8.24 | length 6678.5
  Top Layer w10: P8.24 965,-4175 1140,-4000 1140,-648.29 1380,-408.29 1380,667 P6.4
OUTPUTP25: P7.1 P8.25 | length 4761.6
  Top Layer w10: P8.25 820,-4125 1000,-3945 1000,-2805.11 1000,-1500 1000,-873.73 760,-633.73 760,-340 P7.1
OUTPUTP26: P7.2 P8.26 | length 4746.6
  Top Layer w10: P8.26 821.81,-4075 960,-3936.81 960,-2780.36 960,-1500 960,-890.3 720,-650.29 720,-271 P7.2
OUTPUTP27: P7.3 P8.27 | length 4879.6
  Top Layer w10: P8.27 820,-4025 940,-3905 940,-2735.61 940,-1500 940,-898.58 700,-658.58 700,-182 P7.3
OUTPUTP28: P7.4 P8.28 | length 4863.6
  Top Layer w10: P8.28 820,-3975 900,-3895 900,-2710.86 900,-1500 900,-915.15 660,-675.15 660,-113 P7.4
OUTPUTP29: P8.29 P9.1 | length 5872.2
  Top Layer w10: P8.29 565,-3925 760,-3730 760,-1358.28 520,-1118.28 520,880 P9.1
OUTPUTP30: P8.30 P9.2 | length 5856.2
  Top Layer w10: P8.30 565,-3875 720,-3720 720,-1374.85 480,-1134.85 480,949 P9.2
OUTPUTP31: P8.31 P9.3 | length 5990.2
  Top Layer w10: P8.31 565,-3825 700,-3690 700,-1383.14 460,-1143.14 460,1038 P9.3
OUTPUTP32: P8.32 P9.4 | length 5974.2
  Top Layer w10: P8.32 565,-3775 660,-3680 660,-1399.71 420,-1159.71 420,1050 420,1107 P9.4
RTN: P8.33 P8.34 P8.67 P8.68 P10.1
pads on no net: P1.5 P2.5 P3.5 P4.5 P5.5 P6.5 P7.5 P9.5

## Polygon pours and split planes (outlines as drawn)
GND on InternalPlane1 (split plane): 2579.9,-6979.9 20.1,-6979.9 20.1,-5820.1 50,-5820.1 53.92,-5819.71 57.69,-5818.57 61.17,-5816.71 64.21,-5814.21 66.71,-5811.17 68.57,-5807.69 69.71,-5803.92 70.1,-5800 70.1,-3200 69.71,-3196.08 68.57,-3192.31 66.71,-3188.83 64.21,-3185.79 61.17,-3183.29 57.69,-3181.43 53.92,-3180.29 50,-3179.9 20.1,-3179.9 20.1,2979.9 2579.9,2979.9
RTN on InternalPlane2 (split plane): 2579.9,-6979.9 20.1,-6979.9 20.1,-5820.1 50,-5820.1 53.92,-5819.71 57.69,-5818.57 61.17,-5816.71 64.21,-5814.21 66.71,-5811.17 68.57,-5807.69 69.71,-5803.92 70.1,-5800 70.1,-3200 69.71,-3196.08 68.57,-3192.31 66.71,-3188.83 64.21,-3185.79 61.17,-3183.29 57.69,-3181.43 53.92,-3180.29 50,-3179.9 20.1,-3179.9 20.1,2979.9 2579.9,2979.9
GND on InternalPlane3 (split plane): 2579.9,-6979.9 20.1,-6979.9 20.1,-5820.1 50,-5820.1 53.92,-5819.71 57.69,-5818.57 61.17,-5816.71 64.21,-5814.21 66.71,-5811.17 68.57,-5807.69 69.71,-5803.92 70.1,-5800 70.1,-3200 69.71,-3196.08 68.57,-3192.31 66.71,-3188.83 64.21,-3185.79 61.17,-3183.29 57.69,-3181.43 53.92,-3180.29 50,-3179.9 20.1,-3179.9 20.1,2979.9 2579.9,2979.9

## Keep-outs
Keep-Out Layer:
  the board outline again, w10

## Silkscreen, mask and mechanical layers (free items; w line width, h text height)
Top Overlay:
  rectangle: 1295,-6850 1850,-6505
  rectangle: 1700,2050 2315,2450
  text "Chassis GND Connection" at 1000,2900 h40
  text "ADC AA Interface Board" at 500,2500 h100
  text "D070100" at 500,2350 h100
  text "Rev" at 1450,2350 h100
  text "CH 29-32" at 700,1200 h100 r90
  text "CH 21-24" at 1800,1050 h100 r90
  text "CH 25-28" at 700,-200 h100 r90
  text "CH 17-20" at 1850,-450 h100 r90
  text "CH 13-16" at 1850,-2050 h100 r90
  text "ADC RTN to GND Connection" at 300,-2700 h40
  text "Jumper Nominally Installed" at 300,-2800 h40
  text "CH 9-12" at 1850,-3600 h100 r90
  text "To ADC" at 750,-4750 h100 r90
  text "CH 5-8" at 2120,-4910 h100 r90
  text "CH 1-4" at 1850,-6100 h100 r90
  text "Serial No" at 600,-6600 h100
Mechanical 1:
  lines w10: 0,-7000 0,-5800 50,-5800 50,-4500 50,-3200 0,-3200 0,3000 2600,3000 2600,-7000 0,-7000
